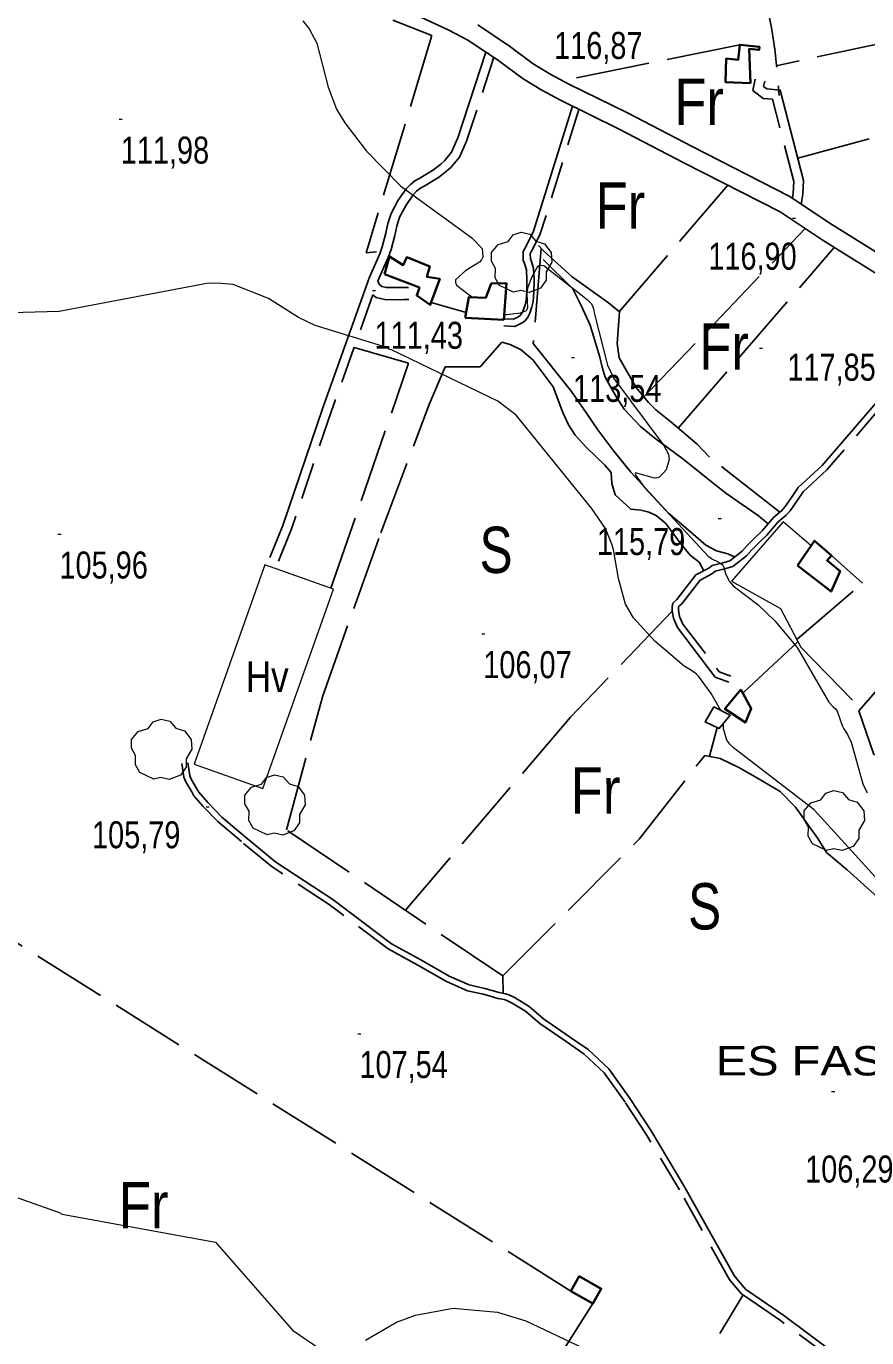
# Model space of a CAD drawing. Extents: x 483840 to 488445, y 4386047 to 4389027.
# Drawn here: x 485701.7 to 485974, y 4387140.8 to 4387565.7 of the extents above; entities that cross this region are included whole.
import ezdxf
from ezdxf.enums import TextEntityAlignment as Align

# ---------------------------------------------------------------- set-up
doc = ezdxf.new("R2010")
doc.units = 0
doc.header["$LTSCALE"] = 4
doc.linetypes.add('LONG_DASHED', pattern=[7.5, 6, -1.5])
doc.linetypes.add('MEDIUM_DASHED', pattern=[4.5, 3, -1.5])
for name, color, linetype, lineweight in [('21', 7, 'Continuous', 25), ('25', 7, 'LONG_DASHED', 25), ('29', 7, 'Continuous', 13), ('30', 7, 'Continuous', 13), ('36', 7, 'Continuous', 25), ('38', 7, 'Continuous', 25), ('47', 7, 'Continuous', 35), ('51', 7, 'Continuous', 13), ('7', 7, 'Continuous', 13), ('9', 7, 'Continuous', 13)]:
    doc.layers.add(name, color=color, linetype=linetype, lineweight=lineweight)
doc.layers.add('31', color=7, linetype='Continuous')
doc.layers.add('5', color=7, linetype='Continuous')

msp = doc.modelspace()

# ---------------------------------------------------------------- linework, layer by layer
at = {"layer": '21'}
msp.add_lwpolyline([(485924.43, 4387345.21), (485921.58, 4387340.3), (485926.21, 4387338.21), (485929.72, 4387342.51)], close=True, dxfattribs=at)
at = {"layer": '25'}
for p, q in [((485932.83, 4387559.69), (485875.28, 4387548.09)), ((485893.81, 4387473.18), (485929, 4387514.19)), ((485901.77, 4387445.64), (485954.07, 4387500.12)), ((485912.91, 4387435.53), (485963.47, 4387494.04)), ((485844.18, 4387473.01), (485832.86, 4387476.23)), ((485951.7, 4387366.3), (485933.81, 4387349.61)), ((485952.62, 4387364.54), (485972.08, 4387344.66)), ((485923.03, 4387329.18), (485925.54, 4387338.52)), ((485885.23, 4387151.92), (485817.05, 4387044.68))]:
    msp.add_line(p, q, dxfattribs=at)
for points in [[(486020.11, 4387607.45), (486080.72, 4387616.63), (486098.81, 4387585.68), (485944.62, 4387552.91)], [(485698.12, 4387612.51), (485726.66, 4387604), (485747.95, 4387597.01), (485774.36, 4387586.43), (485792.48, 4387578.67), (485833.07, 4387562.7), (485811.81, 4387492.32), (485815.11, 4387492.58)], [(485951.63, 4387522.98), (486013.89, 4387539.85), (486084.58, 4387556.17), (486125.82, 4387506.81)], [(485868.45, 4387493.77), (485865.94, 4387462.88), (485878.32, 4387447.4), (485883.17, 4387440.35), (485886.85, 4387434.97), (485891.71, 4387428.52), (485897.53, 4387421.24), (485909.72, 4387408), (485916.17, 4387402.51), (485921.88, 4387397.55), (485925.3, 4387395.7), (485928.97, 4387394.75), (485931.13, 4387393.76)], [(485945.81, 4387408.32), (485923.04, 4387426.05), (485919.05, 4387430.31), (485910.52, 4387437.56), (485905.62, 4387441.46), (485903.26, 4387443.82), (485899.27, 4387448.67), (485893.71, 4387458.28), (485893.1, 4387462.87), (485893.85, 4387473.14), (485890.29, 4387476.04), (485878.55, 4387484.46), (485869.22, 4387492.93), (485867.59, 4387494.68)], [(485869.1, 4387490.08), (485878.8, 4387480.63), (485881.5, 4387475.19), (485884.33, 4387468.85), (485885.05, 4387466.74), (485887.48, 4387458.45), (485888.26, 4387455.21), (485889.27, 4387451.97), (485890.8, 4387449.1), (485892.85, 4387445.54), (485895.35, 4387441.6), (485900.67, 4387436.05), (485905.34, 4387432.3), (485909.87, 4387428.86), (485914.85, 4387425.26), (485918.78, 4387421.98), (485925.68, 4387416.48), (485928.65, 4387414.26), (485932.21, 4387411.73), (485936.74, 4387408.59), (485938.9, 4387407.06), (485942.02, 4387404.46)], [(485856.13, 4387252.42), (485856.02, 4387258.03), (485785.94, 4387305.4), (485797.74, 4387348.83), (485816.51, 4387401.54), (485832.19, 4387443.18), (485837.39, 4387455.41), (485848.72, 4387455.33), (485855.74, 4387463.4), (485858.43, 4387462.62), (485862.01, 4387460.84), (485865.86, 4387457.48), (485872.41, 4387448.91), (485875.52, 4387440.54), (485877.34, 4387436.61), (485879.54, 4387433.27), (485883.09, 4387429.32), (485889.08, 4387423.46), (485891.15, 4387421.1), (485891.4, 4387417.57), (485892.47, 4387413.88), (485897.58, 4387409.3), (485900.8, 4387408.88), (485903.42, 4387408.24), (485905.73, 4387407.16), (485908.85, 4387404.57), (485913.78, 4387397.97), (485916.8, 4387394.32), (485919.7, 4387392.03), (485921.24, 4387389.29)], [(485800.39, 4387383.61), (485825.55, 4387456.56), (485807.92, 4387461.66)], [(486026.94, 4387288.29), (486008.21, 4387300.94), (485999.28, 4387311.5), (485989.67, 4387321.47), (485981.98, 4387329.53), (485976.28, 4387329.76), (485971.46, 4387343.94), (486057.15, 4387442.22)], [(485951.3, 4387367.06), (485972.65, 4387385.27), (485962.58, 4387394.19)], [(485910.97, 4387376.23), (485878.01, 4387341.83), (485824.5, 4387279.34)], [(485856.02, 4387258.03), (485900.25, 4387302.34), (485921.5, 4387329.5), (485926.44, 4387328.45), (485932.48, 4387325.51), (485938.58, 4387322.12), (485945.87, 4387317.82), (485950.9, 4387312.72), (485958.11, 4387302.56), (485960.97, 4387298.02), (485967.64, 4387292.37), (485977.42, 4387283.52)], [(485878.12, 4387155.96), (485676.22, 4387282.81), (485668.15, 4387269.8), (485661.34, 4387265.77), (485657.86, 4387263.57), (485654.46, 4387262.04), (485648.99, 4387262.72), (485624.59, 4387277.32), (485576.29, 4387206.73)], [(485976.06, 4387028.86), (485895.5, 4387090.8), (485933.9, 4387154.73)]]:
    msp.add_lwpolyline(points, dxfattribs=at)
at = {"layer": '29'}
for points in [[(485859.58, 4387479.56), (485855.04, 4387481.68), (485853.63, 4387484.22), (485853.73, 4387487.2), (485852.36, 4387489.61), (485852.4, 4387492.36), (485854.56, 4387494.96), (485857.75, 4387495.96), (485859.4, 4387498.15), (485861.97, 4387498.98), (485864.83, 4387498.33), (485866.78, 4387496.06), (485869.59, 4387495.24), (485871.72, 4387492.39), (485871.96, 4387489.26), (485870.08, 4387486.11), (485870.08, 4387483.43), (485868.26, 4387480.82), (485864.64, 4387479.48), (485861.87, 4387480.11)], [(485742.96, 4387321.78), (485738.42, 4387323.9), (485737.01, 4387326.44), (485737.11, 4387329.42), (485735.74, 4387331.83), (485735.78, 4387334.58), (485737.94, 4387337.18), (485741.13, 4387338.18), (485742.78, 4387340.37), (485745.35, 4387341.2), (485748.21, 4387340.55), (485750.16, 4387338.28), (485752.97, 4387337.46), (485755.1, 4387334.61), (485755.34, 4387331.48), (485753.46, 4387328.33), (485753.46, 4387325.65), (485751.64, 4387323.04), (485748.02, 4387321.7), (485745.25, 4387322.33)], [(485779.7, 4387303.77), (485775.16, 4387305.89), (485773.75, 4387308.43), (485773.85, 4387311.41), (485772.48, 4387313.82), (485772.52, 4387316.57), (485774.68, 4387319.17), (485777.87, 4387320.17), (485779.52, 4387322.36), (485782.09, 4387323.19), (485784.95, 4387322.54), (485786.9, 4387320.27), (485789.71, 4387319.45), (485791.84, 4387316.6), (485792.08, 4387313.47), (485790.2, 4387310.32), (485790.2, 4387307.64), (485788.38, 4387305.03), (485784.76, 4387303.69), (485781.99, 4387304.32)], [(485960.91, 4387298.7), (485956.37, 4387300.82), (485954.96, 4387303.36), (485955.06, 4387306.34), (485953.69, 4387308.75), (485953.73, 4387311.5), (485955.89, 4387314.1), (485959.08, 4387315.1), (485960.73, 4387317.29), (485963.3, 4387318.12), (485966.16, 4387317.47), (485968.11, 4387315.2), (485970.92, 4387314.38), (485973.05, 4387311.53), (485973.29, 4387308.4), (485971.41, 4387305.25), (485971.41, 4387302.57), (485969.59, 4387299.96), (485965.97, 4387298.62), (485963.2, 4387299.25)]]:
    msp.add_lwpolyline(points, close=True, dxfattribs=at)
at = {"layer": '30'}
msp.add_lwpolyline([(485778.99, 4387391.19), (485756.11, 4387326.67), (485778.33, 4387318.79), (485801.21, 4387383.31)], close=True, dxfattribs=at)
at = {"layer": '36'}
for points in [[(485818.02, 4387573.92), (485838.32, 4387564.52), (485844.92, 4387561.11), (485854.8, 4387554.47), (485862.63, 4387548.64), (485868.7, 4387544.98), (485874.73, 4387541.7), (485893.77, 4387532.39), (485914.74, 4387521.47), (485945.9, 4387505.54), (485959.53, 4387496.48), (485982.5, 4387482.18)], [(485847.92, 4387566.17), (485858.19, 4387559.27), (485865.91, 4387553.53), (485871.63, 4387550.07), (485877.42, 4387546.92), (485896.42, 4387537.64), (485917.43, 4387526.69), (485948.87, 4387510.62), (485962.71, 4387501.42), (485985.53, 4387487.21)]]:
    msp.add_lwpolyline(points, dxfattribs=at)
at = {"layer": '38'}
for points in [[(485850.6, 4387557.29), (485841.5, 4387529.51), (485839.41, 4387524.85), (485837.2, 4387522.09), (485835.94, 4387520.99), (485833.59, 4387519.13), (485829.14, 4387516.48), (485827.53, 4387515.62), (485826.12, 4387514.42), (485824.72, 4387513.05), (485822.17, 4387509.34), (485819.85, 4387505.01), (485818.86, 4387501.74), (485818.14, 4387498.64), (485817.03, 4387494.21), (485816.21, 4387491.92), (485812.88, 4387484.38), (485797.77, 4387442.09), (485784.78, 4387403.95), (485780.59, 4387393.54)], [(485952.75, 4387508.04), (485953.27, 4387511.28), (485953.5, 4387515.72), (485945.93, 4387544.97), (485941.63, 4387545.4), (485940.56, 4387546.21), (485940.94, 4387547.87)], [(485878.63, 4387539.79), (485866.06, 4387499.28), (485863.65, 4387494.5), (485862.63, 4387492.69), (485862.69, 4387489.95), (485863.11, 4387488.78), (485863.7, 4387486.81), (485863.86, 4387483.43), (485863.81, 4387479.76), (485863.62, 4387476.86), (485863.27, 4387475.46), (485862.7, 4387473.62), (485862.2, 4387472.72), (485861.64, 4387471.96), (485860.95, 4387471.49), (485859.49, 4387470.76), (485856.52, 4387470.94)], [(485815.59, 4387483.17), (485816.03, 4387482.09), (485816.83, 4387481.4), (485818.35, 4387481.05), (485820.93, 4387481.02), (485823.9, 4387481.05), (485825.53, 4387481.09)], [(486000.36, 4387470.79), (485959.58, 4387423.41), (485951.78, 4387416.26), (485949.63, 4387413.03), (485947.54, 4387410.07), (485946.42, 4387408.84), (485943.82, 4387406.61), (485940.13, 4387402.21), (485937.81, 4387400.03), (485935.27, 4387397.48), (485933.57, 4387395.62), (485929.57, 4387392.56), (485927.02, 4387391.78), (485925.23, 4387391.36), (485923.92, 4387391), (485922.83, 4387390.11), (485918.63, 4387387.94), (485912.49, 4387380.01), (485911.17, 4387378.82), (485910.88, 4387377.7), (485910.95, 4387376.33), (485911.32, 4387373.94), (485912.61, 4387370.96), (485924.9, 4387354.87), (485929.24, 4387353.19)], [(485962.83, 4387136.28), (485947.14, 4387147.99), (485939.92, 4387152.99), (485934.76, 4387156.5), (485932.35, 4387159.36), (485931.02, 4387160.95), (485914.96, 4387189.69), (485904.1, 4387207.88), (485897.32, 4387218.22), (485890.4, 4387227.96), (485883.67, 4387234.19), (485877.67, 4387238.36), (485869.24, 4387244.16), (485864.62, 4387248.15), (485860.03, 4387250.99), (485858.05, 4387251.89), (485856.96, 4387252.26), (485854.92, 4387252.66), (485852.19, 4387253.44), (485850.22, 4387254.01), (485845.2, 4387255.11), (485838.72, 4387257.98), (485829.54, 4387263.27), (485819.99, 4387268.48), (485800.94, 4387282.76), (485782.53, 4387294.94), (485772.64, 4387303.07), (485765.05, 4387309.51), (485760.46, 4387314.25), (485757.59, 4387317.57), (485756.98, 4387318.61), (485755.11, 4387321.82), (485754.62, 4387322.97), (485754.02, 4387327.12)]]:
    msp.add_lwpolyline(points, dxfattribs=at)
at = {"layer": '38', "linetype": 'MEDIUM_DASHED'}
for points in [[(485853.2, 4387555.66), (485844.28, 4387528.44), (485841.98, 4387523.29), (485839.36, 4387520.01), (485837.84, 4387518.7), (485835.28, 4387516.68), (485830.6, 4387513.88), (485829.22, 4387513.14), (485828.13, 4387512.21), (485827.01, 4387511.12), (485824.72, 4387507.78), (485822.61, 4387503.87), (485821.74, 4387500.97), (485821.03, 4387497.94), (485819.89, 4387493.35), (485818.97, 4387490.81), (485815.59, 4387483.17)], [(485949.88, 4387510.11), (485950.12, 4387511.62), (485950.31, 4387515.4), (485943.41, 4387542.04), (485940.44, 4387542.33), (485937.02, 4387544.9), (485937.84, 4387548.57)], [(485880.74, 4387538.76), (485868.22, 4387498.41), (485865.7, 4387493.41), (485864.96, 4387492.1), (485865, 4387490.38), (485865.32, 4387489.51), (485866, 4387487.2), (485866.18, 4387483.46), (485866.13, 4387479.67), (485865.92, 4387476.5), (485865.51, 4387474.83), (485864.84, 4387472.7), (485864.15, 4387471.46), (485863.26, 4387470.26), (485862.12, 4387469.49), (485859.98, 4387468.41), (485856.38, 4387468.62)], [(485814, 4387478.69), (485800.58, 4387441.11), (485787.57, 4387402.91), (485783.35, 4387392.43)], [(485814, 4387478.69), (485815.01, 4387477.82), (485817.88, 4387477.16), (485820.93, 4387477.11), (485823.98, 4387477.14), (485825.65, 4387477.2)], [(486001.94, 4387469.43), (485961.08, 4387421.96), (485953.37, 4387414.9), (485951.35, 4387411.86), (485949.17, 4387408.76), (485947.87, 4387407.34), (485945.31, 4387405.14), (485941.65, 4387400.78), (485939.26, 4387398.54), (485936.78, 4387396.05), (485934.98, 4387394.08), (485930.54, 4387390.68), (485927.57, 4387389.77), (485925.74, 4387389.34), (485924.9, 4387389.11), (485923.98, 4387388.36), (485919.99, 4387386.3), (485914.03, 4387378.59), (485913.03, 4387377.69), (485912.97, 4387377.49), (485913.02, 4387376.54), (485913.34, 4387374.52), (485914.42, 4387372.02), (485926.19, 4387356.6), (485929.99, 4387355.13)], [(485961.66, 4387134.71), (485946, 4387146.4), (485938.81, 4387151.37), (485933.44, 4387155.04), (485930.85, 4387158.1), (485929.4, 4387159.83), (485913.27, 4387188.71), (485902.44, 4387206.85), (485895.7, 4387217.12), (485888.92, 4387226.66), (485882.44, 4387232.66), (485876.55, 4387236.76), (485868.05, 4387242.61), (485863.46, 4387246.57), (485859.1, 4387249.26), (485857.34, 4387250.07), (485856.46, 4387250.36), (485854.46, 4387250.76), (485851.65, 4387251.56), (485849.74, 4387252.11), (485844.59, 4387253.24), (485837.83, 4387256.23), (485828.58, 4387261.56), (485818.93, 4387266.83), (485799.82, 4387281.16), (485781.37, 4387293.36), (485771.39, 4387301.57), (485763.71, 4387308.08), (485759.02, 4387312.93), (485755.99, 4387316.43), (485755.29, 4387317.63), (485753.36, 4387320.93), (485752.72, 4387322.44), (485752.08, 4387326.84)]]:
    msp.add_lwpolyline(points, dxfattribs=at)
at = {"layer": '38', "linetype": 'LONG_DASHED'}
msp.add_spline([(485835.79, 4387757.61), (485832.21, 4387753.53), (485836.43, 4387728.63), (485841.09, 4387708.61), (485870.67, 4387714.86), (485898.06, 4387719.87), (485902.21, 4387721.39), (485912.8, 4387685.45), (485922.23, 4387652.37), (485927.96, 4387633.68), (485937.96, 4387587.76), (485943.87, 4387560.52), (485945.58, 4387543.23)], degree=3, dxfattribs=at)
at = {"layer": '47'}
for points in [[(485936.33, 4387547.27), (485928.16, 4387547.61), (485928.47, 4387555.24), (485932.35, 4387554.85), (485932.83, 4387559.69), (485939.19, 4387559.03), (485939.08, 4387558.04), (485935.91, 4387558.38)], [(485817.71, 4387485.34), (485829.05, 4387481.05), (485828.19, 4387478.43), (485832.58, 4387475.44), (485835.62, 4387483.88), (485831.5, 4387484.46), (485832.38, 4387487.9), (485824.99, 4387490.93), (485823.83, 4387488.32), (485819.37, 4387491.09)], [(485843.85, 4387471.23), (485856.37, 4387470.6), (485857.21, 4387482.44), (485852.33, 4387482.36), (485850.54, 4387477.66), (485845.07, 4387477.96)], [(485951.58, 4387391.05), (485962.41, 4387382.56), (485965.36, 4387389.2), (485961.13, 4387392.64), (485962.58, 4387394.19), (485957.09, 4387399)], [(485933.14, 4387350.79), (485928.02, 4387344.56), (485934.64, 4387340.19), (485936.58, 4387344.66)], [(485878.12, 4387155.96), (485885.23, 4387151.92), (485887.96, 4387156.72), (485880.85, 4387160.76)]]:
    msp.add_lwpolyline(points, close=True, dxfattribs=at)
at = {"layer": '51'}
msp.add_lwpolyline([(485955.98, 4387397.4), (485946.9, 4387405.15), (485930.19, 4387385.95), (485946.05, 4387377.02), (485952.62, 4387364.54)], dxfattribs=at)
at = {"layer": '7'}
for p, q in [((485850.43, 4387557.03), (485851.43, 4387557.03)), ((485731.79, 4387535.56), (485732.79, 4387535.56)), ((485949.89, 4387503.53), (485950.89, 4387503.53)), ((485813.83, 4387480.06), (485814.83, 4387480.06)), ((485939.22, 4387461.35), (485940.22, 4387461.35)), ((485878.32, 4387458.37), (485879.32, 4387458.37)), ((485925.88, 4387406.17), (485926.88, 4387406.17)), ((485711.93, 4387401.15), (485712.93, 4387401.15)), ((485849.23, 4387368.87), (485850.23, 4387368.87)), ((485759.96, 4387312.82), (485760.96, 4387312.82)), ((485809.11, 4387239.33), (485810.11, 4387239.33)), ((485962.59, 4387220.62), (485963.59, 4387220.62))]:
    msp.add_line(p, q, dxfattribs=at)
at = {"layer": '9'}
for points in [[(485791.26, 4387567.44), (485793.36, 4387564.89), (485795.83, 4387560.16), (485799.49, 4387545.91), (485802.16, 4387538.88), (485804.84, 4387534.4), (485811.88, 4387525.25), (485823.03, 4387513.91), (485846.08, 4387497.13), (485849.35, 4387493.67), (485849.6, 4387490.85), (485849.15, 4387490.07), (485848.46, 4387489.3), (485844.1, 4387486.52), (485840.77, 4387483.58), (485840.74, 4387482.7), (485841.1, 4387481.8), (485845.6, 4387478.32), (485846.37, 4387477.89)], [(485856.5, 4387472.36), (485857.31, 4387472.27), (485861.84, 4387472.81), (485863.69, 4387473.62), (485863.98, 4387473.99), (485864.18, 4387474.41), (485863.91, 4387479.14), (485864.22, 4387480.92), (485865.54, 4387484.6), (485867.21, 4387487.58), (485867.63, 4387488.04), (485868.03, 4387488.34), (485869.31, 4387488.14), (485883.35, 4387477.18), (485884.67, 4387475.82), (485885.13, 4387475.15), (485885.49, 4387474.13), (485885.73, 4387472.39), (485889.94, 4387455.88), (485892.07, 4387451.59), (485908.25, 4387429.86), (485909.75, 4387427.06), (485909.89, 4387426.22), (485909.91, 4387425.36), (485909.01, 4387422.04), (485906.84, 4387419.65), (485906.06, 4387419.38), (485905.21, 4387419.28), (485899.01, 4387420.99), (485898.93, 4387420.66), (485899.12, 4387420.1)], [(485926.63, 4387344.09), (485926.59, 4387344.21), (485923.54, 4387349.52), (485919.42, 4387355.11), (485918.79, 4387355.83), (485917.25, 4387356.97), (485914.85, 4387358.41), (485905.33, 4387366.44), (485898.42, 4387374.07), (485895.86, 4387378.47), (485893.52, 4387386.74), (485891.92, 4387396.19), (485891.43, 4387397.89), (485889.3, 4387402.94), (485884.77, 4387409.53), (485860.41, 4387439.67), (485854.43, 4387444.18), (485819.99, 4387460.88), (485819.34, 4387460.99), (485819.17, 4387461.06), (485819.01, 4387461.14), (485818.44, 4387461.58), (485795.27, 4387468.72), (485789.86, 4387471.34), (485780.18, 4387477.44), (485768.68, 4387482), (485764.83, 4387482.4), (485760.7, 4387482.42), (485712.3, 4387473.27), (485669.44, 4387472.13)], [(485899.12, 4387420.1), (485902, 4387416.23), (485922.61, 4387394.05), (485923.67, 4387393.26), (485924.01, 4387393.05), (485925.83, 4387392.21), (485927.17, 4387391.27), (485927.45, 4387390.88), (485927.69, 4387390.44), (485928.23, 4387388.4), (485929.35, 4387385.89), (485930.68, 4387384.38), (485938.67, 4387378.33), (485944.23, 4387373.11), (485951.41, 4387364.42), (485961.68, 4387346.74), (485962.99, 4387345.37), (485963.9, 4387344.59), (485964.37, 4387343.77), (485966.01, 4387339.21), (485966.56, 4387338.06), (485967.69, 4387336.29), (485968.94, 4387333.78), (485972.74, 4387320.25), (485974.1, 4387317.38)], [(486060.42, 4387188.91), (486059.6, 4387190.36), (486058.72, 4387192.57), (486057.84, 4387194.19), (486057.46, 4387194.6), (486057.02, 4387194.99), (486054.91, 4387196.25), (486052.07, 4387197.65), (486051.35, 4387198.17), (486020.45, 4387225.68), (486017.89, 4387228.94), (486017.67, 4387230.3), (486017.4, 4387231.08), (486006.44, 4387256.19), (486002.28, 4387262.08), (485956.91, 4387311.88), (485930.84, 4387331.88), (485929.59, 4387333.17), (485928.63, 4387334.38), (485927.58, 4387338.05), (485927.52, 4387339.82)], [(485670.16, 4387196.25), (485712.6, 4387181.29), (485713.03, 4387181.01), (485713.31, 4387180.91), (485763.02, 4387171.81), (485787.89, 4387143.25), (485797.14, 4387137)], [(485811.58, 4387140.07), (485821.6, 4387145.92), (485827.76, 4387148.17), (485839.96, 4387150.46), (485854.3, 4387149.15), (485863.47, 4387146.33), (485882.23, 4387137.43)]]:
    msp.add_lwpolyline(points, dxfattribs=at)

# ---------------------------------------------------------------- texts
at = {"layer": '31'}
for s, height, width, p in [('Fr', 15, 0.85, (485919.69, 4387533.7)), ('Fr', 15, 0.85, (485894.17, 4387500.1)), ('Fr', 15, 0.85, (485927.75, 4387454.42)), ('S', 15, 0.8, (485853.88, 4387388.57)), ('Hv', 10, 0.85, (485779.73, 4387349.97)), ('Fr', 15, 0.85, (485886.11, 4387310.63)), ('S', 15, 0.8, (485921.46, 4387273.1)), ('Fr', 15, 0.85, (485739.71, 4387176.26))]:
    msp.add_text(s, height=height, dxfattribs=dict(at, width=width)).set_placement(p, align=Align.CENTER)
at = {"layer": '5', "width": 1.2}
msp.add_text('ES FASSARET', height=9.5, dxfattribs=at).set_placement((486030.11, 4387225.8), align=Align.RIGHT)
at = {"layer": '7', "width": 0.8}
for s, p in [('116,87', (485872.69, 4387555.1)), ('111,98', (485732.29, 4387521.19)), ('116,90', (485922.64, 4387486.83)), ('111,43', (485814.52, 4387461.19)), ('117,85', (485948.26, 4387450.87)), ('113,54', (485878.82, 4387444)), ('115,79', (485886.55, 4387394.37)), ('105,96', (485712.43, 4387386.78)), ('106,07', (485849.73, 4387354.5)), ('105,79', (485722.97, 4387299.4)), ('107,54', (485809.61, 4387224.96)), ('106,29', (485954.02, 4387191.11))]:
    msp.add_text(s, height=8.75, dxfattribs=at).set_placement(p)

doc.saveas('drawing.dxf')
